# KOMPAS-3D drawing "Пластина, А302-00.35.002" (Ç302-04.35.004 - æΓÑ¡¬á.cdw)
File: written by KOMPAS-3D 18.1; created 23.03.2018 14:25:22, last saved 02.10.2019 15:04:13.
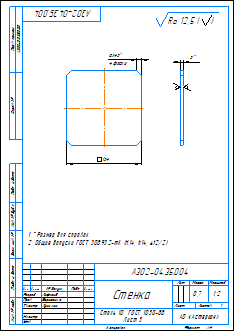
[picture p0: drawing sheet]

Sheet 1: A4, portrait

Document properties: Автор: Милов; Полное имя файла: D:\Мембранные насосы\Мембранный электропривод\А302-00.00.000 - ASTRA-302 (МЭ200)\А302-04.00.000 - Мембранный насос ASTRA-302-PP Чертежи\А302-04.35.004 - Стенка.cdw; Масса: 0.697075

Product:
- Part/product: Пластина  | designation А302-00.35.002
    Масса: 0.697075
    Раздел спецификации: Детали
    Форматы листов документа: A4
  - Component: Пластина  | designation А302-00.35.002  | Масса: 0.7; Раздел спецификации: Детали; Форматы листов документа: A4
- Part/product: Пластина  | designation А302-04.35.002
    Масса: 1.32755
    Раздел спецификации: Детали
    Форматы листов документа: A4
- Part/product: Пластина  | designation А302-05.35.002
    Масса: 0.658749
    Раздел спецификации: Детали
    Форматы листов документа: A4
- Part/product: Пластина  | designation А302-00.35.002-01
    Масса: 1.44135
    Раздел спецификации: Детали
    Форматы листов документа: A4

Title block, sheet 1: Наименование: Стенка; designation: А302-04.35.004; Материал: Сталь 10  ГОСТ 1050-88 / Лист 5; Масса: 0,7; scale: 1:2; Количество листов документа: 1; organisation: АО «Астерион»; Форматы листов документа: A4; stored path: \\192.168.87.28\Konstructor_doc\Мембранные насосы\Мембранный электропривод\А302-00.00.000 - ASTRA-302 (МЭ200)\Чертежи\А302-00.35.002 - Пластина.cdw; Разработал: Лифлянд; Проверил: Борисенко; Т. контр.: Лучихин

Views: Вид 1, Спереди, Проекционный вид 2
Referenced files in Z:\Мембранные насосы\Мембранный электропривод\А302-00.00.000 - ASTRA-302 (МЭ200)\3Д\: А302-00.35.002 - Пластина.m3d
Referenced files in D:\Мембранные насосы\Мембранный электропривод\А302-00.00.000 - ASTRA-302 (МЭ200)\3Д\: А302-00.35.002 - Пластина.m3d
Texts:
  Ra 12,5
  Ra 12,5 ( )
  Пластина
Dimensions and other numbers on the sheet: 134; 8; 4 фаски; 5; 1:2; 1; 0,7

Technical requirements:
  *Размер для справок.
  Общие допуски ГОСТ 30893.2-mK (H14, h14,  t2/2).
